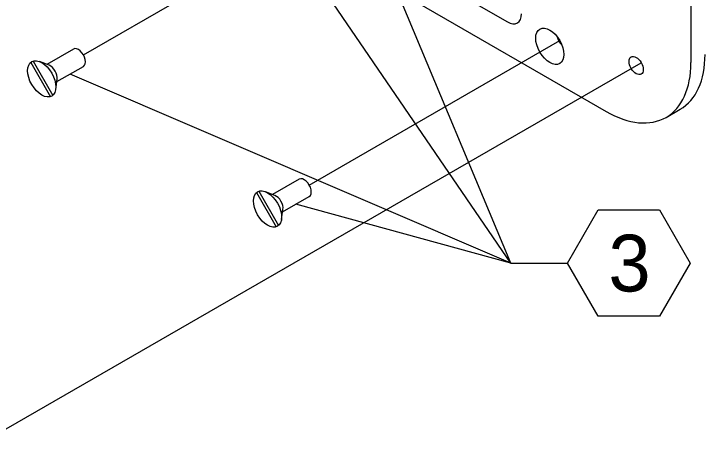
# Model space of a CAD drawing. Extents: x 99862 to 103151, y 100000 to 105076.
# Drawn here: x 100962.8 to 101157.1, y 103339.3 to 103460 of the extents above; entities that cross this region are included whole.
import ezdxf

# ---------------------------------------------------------------- set-up
doc = ezdxf.new("R2010")
doc.units = 0
for name, color, linetype in [('Level 15', 7, 'Continuous'), ('Level 16', 7, 'Continuous'), ('Level 20', 7, 'Continuous'), ('Level 41', 7, 'Continuous')]:
    doc.layers.add(name, color=color, linetype=linetype)

msp = doc.modelspace()

# ---------------------------------------------------------------- linework, layer by layer
at = {"layer": 'Level 15'}
for q in [(100978.65, 103571.56), (101042.29, 103534.82), (100978.65, 103442.96), (101042.29, 103406.22), (101118.82, 103389.59)]:
    msp.add_line((101102.82, 103389.59), q, dxfattribs=at)
at = {"layer": 'Level 16'}
for p, q in [((100982.4, 103448.37), (101053.01, 103489.14)), ((101046.04, 103411.63), (101116.65, 103452.4)), ((100954.54, 103339.32), (101139.59, 103446.16))]:
    msp.add_line(p, q, dxfattribs=at)
at = {"layer": 'Level 20'}
msp.add_lwpolyline([(101118.82, 103389.59), (101127.48, 103404.58), (101144.8, 103404.58), (101153.45, 103389.59), (101144.8, 103374.59), (101127.48, 103374.59), (101118.82, 103389.59)], dxfattribs=at)
at = {"layer": 'Level 41'}
for p, q in [((101153.61, 103676.19), (101153.61, 103446.18)), ((101034.29, 103487.52), (101129.75, 103432.4)), ((101062.13, 103480.63), (101101.9, 103457.66)), ((100979.58, 103450), (100972.09, 103445.67)), ((100968.18, 103446.62), (100973.77, 103436.94)), ((100972.73, 103445.41), (100970.03, 103446.48)), ((100967.53, 103446.24), (100973.12, 103436.56)), ((100974.9, 103440.8), (100982.4, 103445.12)), ((100974.58, 103438.61), (100975, 103441.48)), ((101146.62, 103430.73), (101150.6, 103433.03)), ((101043.22, 103413.25), (101035.73, 103408.93)), ((101031.17, 103409.5), (101036.76, 103399.82)), ((101031.82, 103409.87), (101037.41, 103400.2)), ((101036.37, 103408.67), (101033.67, 103409.74)), ((101038.54, 103404.05), (101046.04, 103408.38)), ((101038.22, 103401.87), (101038.64, 103404.74))]:
    msp.add_line(p, q, dxfattribs=at)
for centre, major_axis, start_param, end_param in [((101101.9, 103462.26), (-2.81, 4.87), 2.356194, 3.926991), ((101117.81, 103453.07), (-1.41, 2.44), 1.084101, 2.057491), ((100980.99, 103447.56), (1.41, -2.44), 6.28318, 9.424778), ((100980.99, 103447.56), (1.41, -2.44), 3.141593, 3.141605), ((101133.72, 103462.26), (16.88, -29.23), 0, 0.785398), ((100973.03, 103442.97), (1.41, -2.44), 0.630137, 2.511455), ((101129.75, 103459.96), (16.88, -29.23), 6.283185, 7.068583), ((101129.75, 103459.96), (16.88, -29.23), 5.497787, 6.283185), ((101044.63, 103410.82), (1.41, -2.44), 6.28318, 9.424778), ((101044.63, 103410.82), (1.41, -2.44), 3.141593, 3.141605), ((101036.67, 103406.23), (1.41, -2.44), 0.630137, 2.511455)]:
    msp.add_ellipse(centre, major_axis=major_axis, ratio=0.57735, start_param=start_param, end_param=end_param, dxfattribs=at)
for centre, major_axis in [((101113.84, 103450.78), (-2.81, 4.87)), ((100970.65, 103441.59), (-2.81, 4.87)), ((101138.18, 103445.35), (-1.41, 2.44)), ((101034.29, 103404.85), (-2.81, 4.87))]:
    msp.add_ellipse(centre, major_axis=major_axis, ratio=0.57735, dxfattribs=at)

# ---------------------------------------------------------------- texts
at = {"layer": 'Level 20'}
msp.add_text('3', height=16, dxfattribs=at).set_placement((101130.36, 103381.59))

doc.saveas('drawing.dxf')
